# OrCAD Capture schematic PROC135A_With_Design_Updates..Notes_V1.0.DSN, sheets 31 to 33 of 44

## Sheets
31 31. SOC WKUP & GPMC: size C; title: SOC WKUP & GPMC
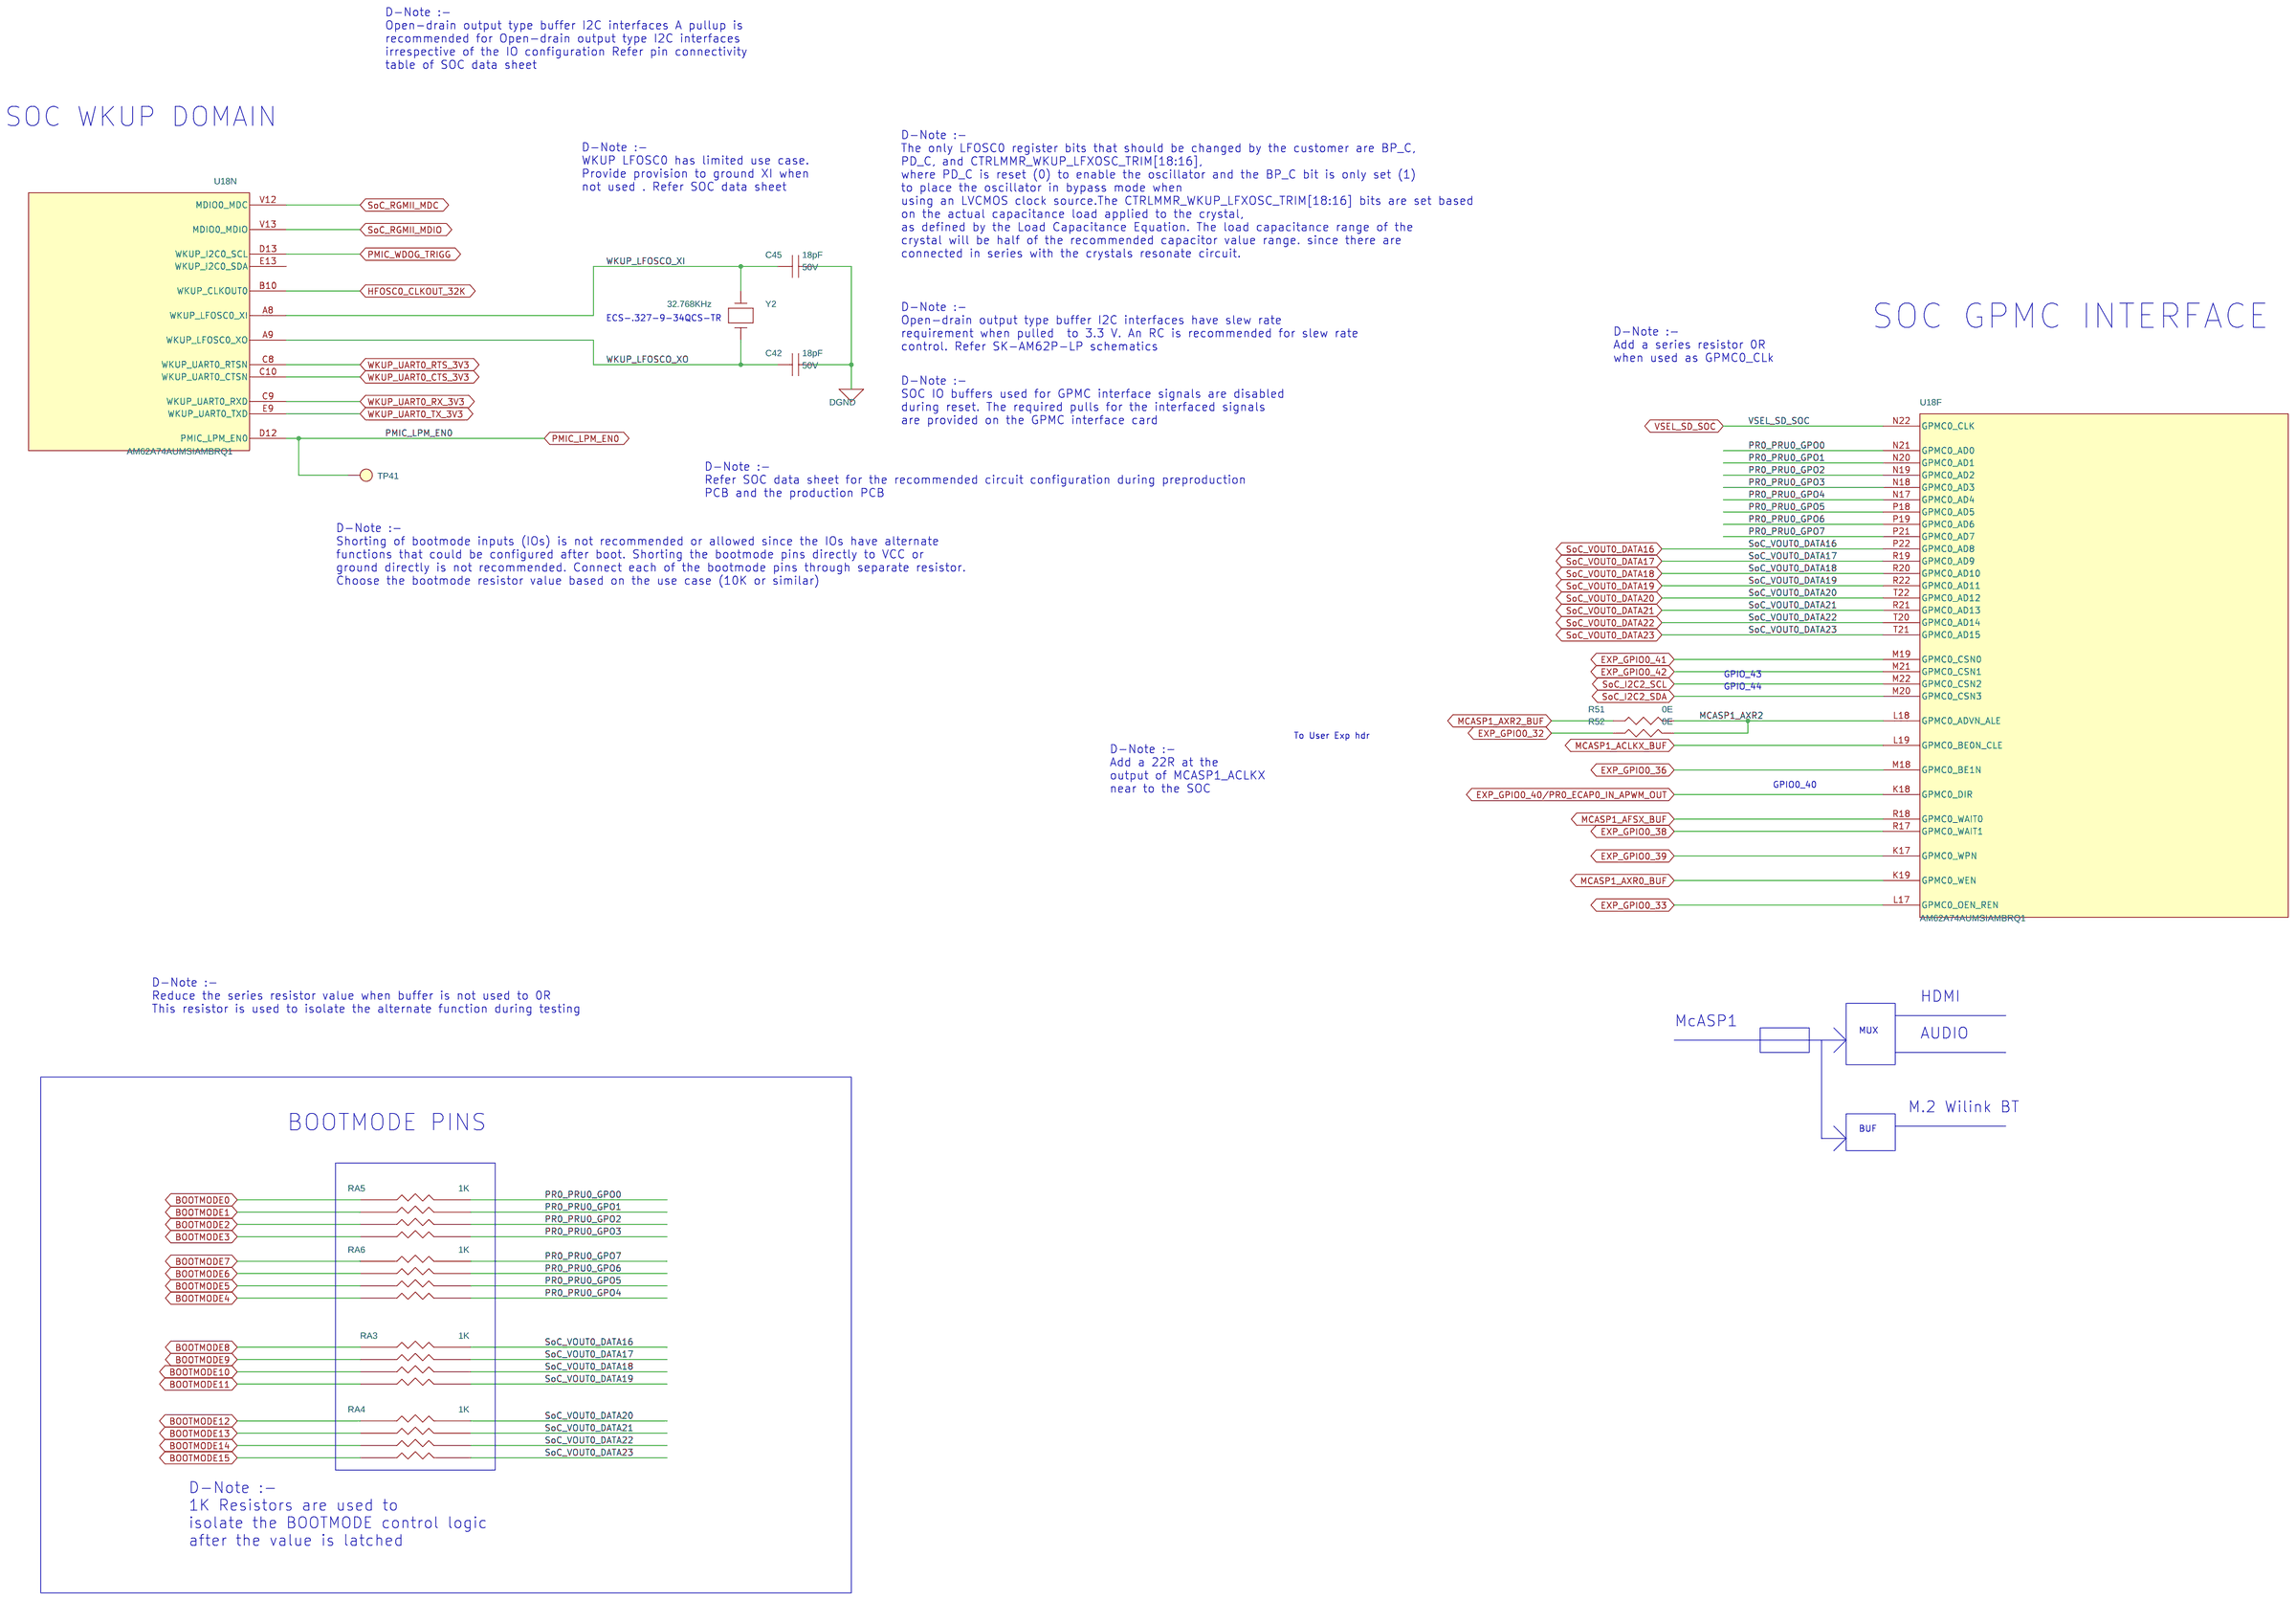
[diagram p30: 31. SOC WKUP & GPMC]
32 32. USER EXPANSION CONNECTOR: size C; title: USER EXPANSION CONNECTOR
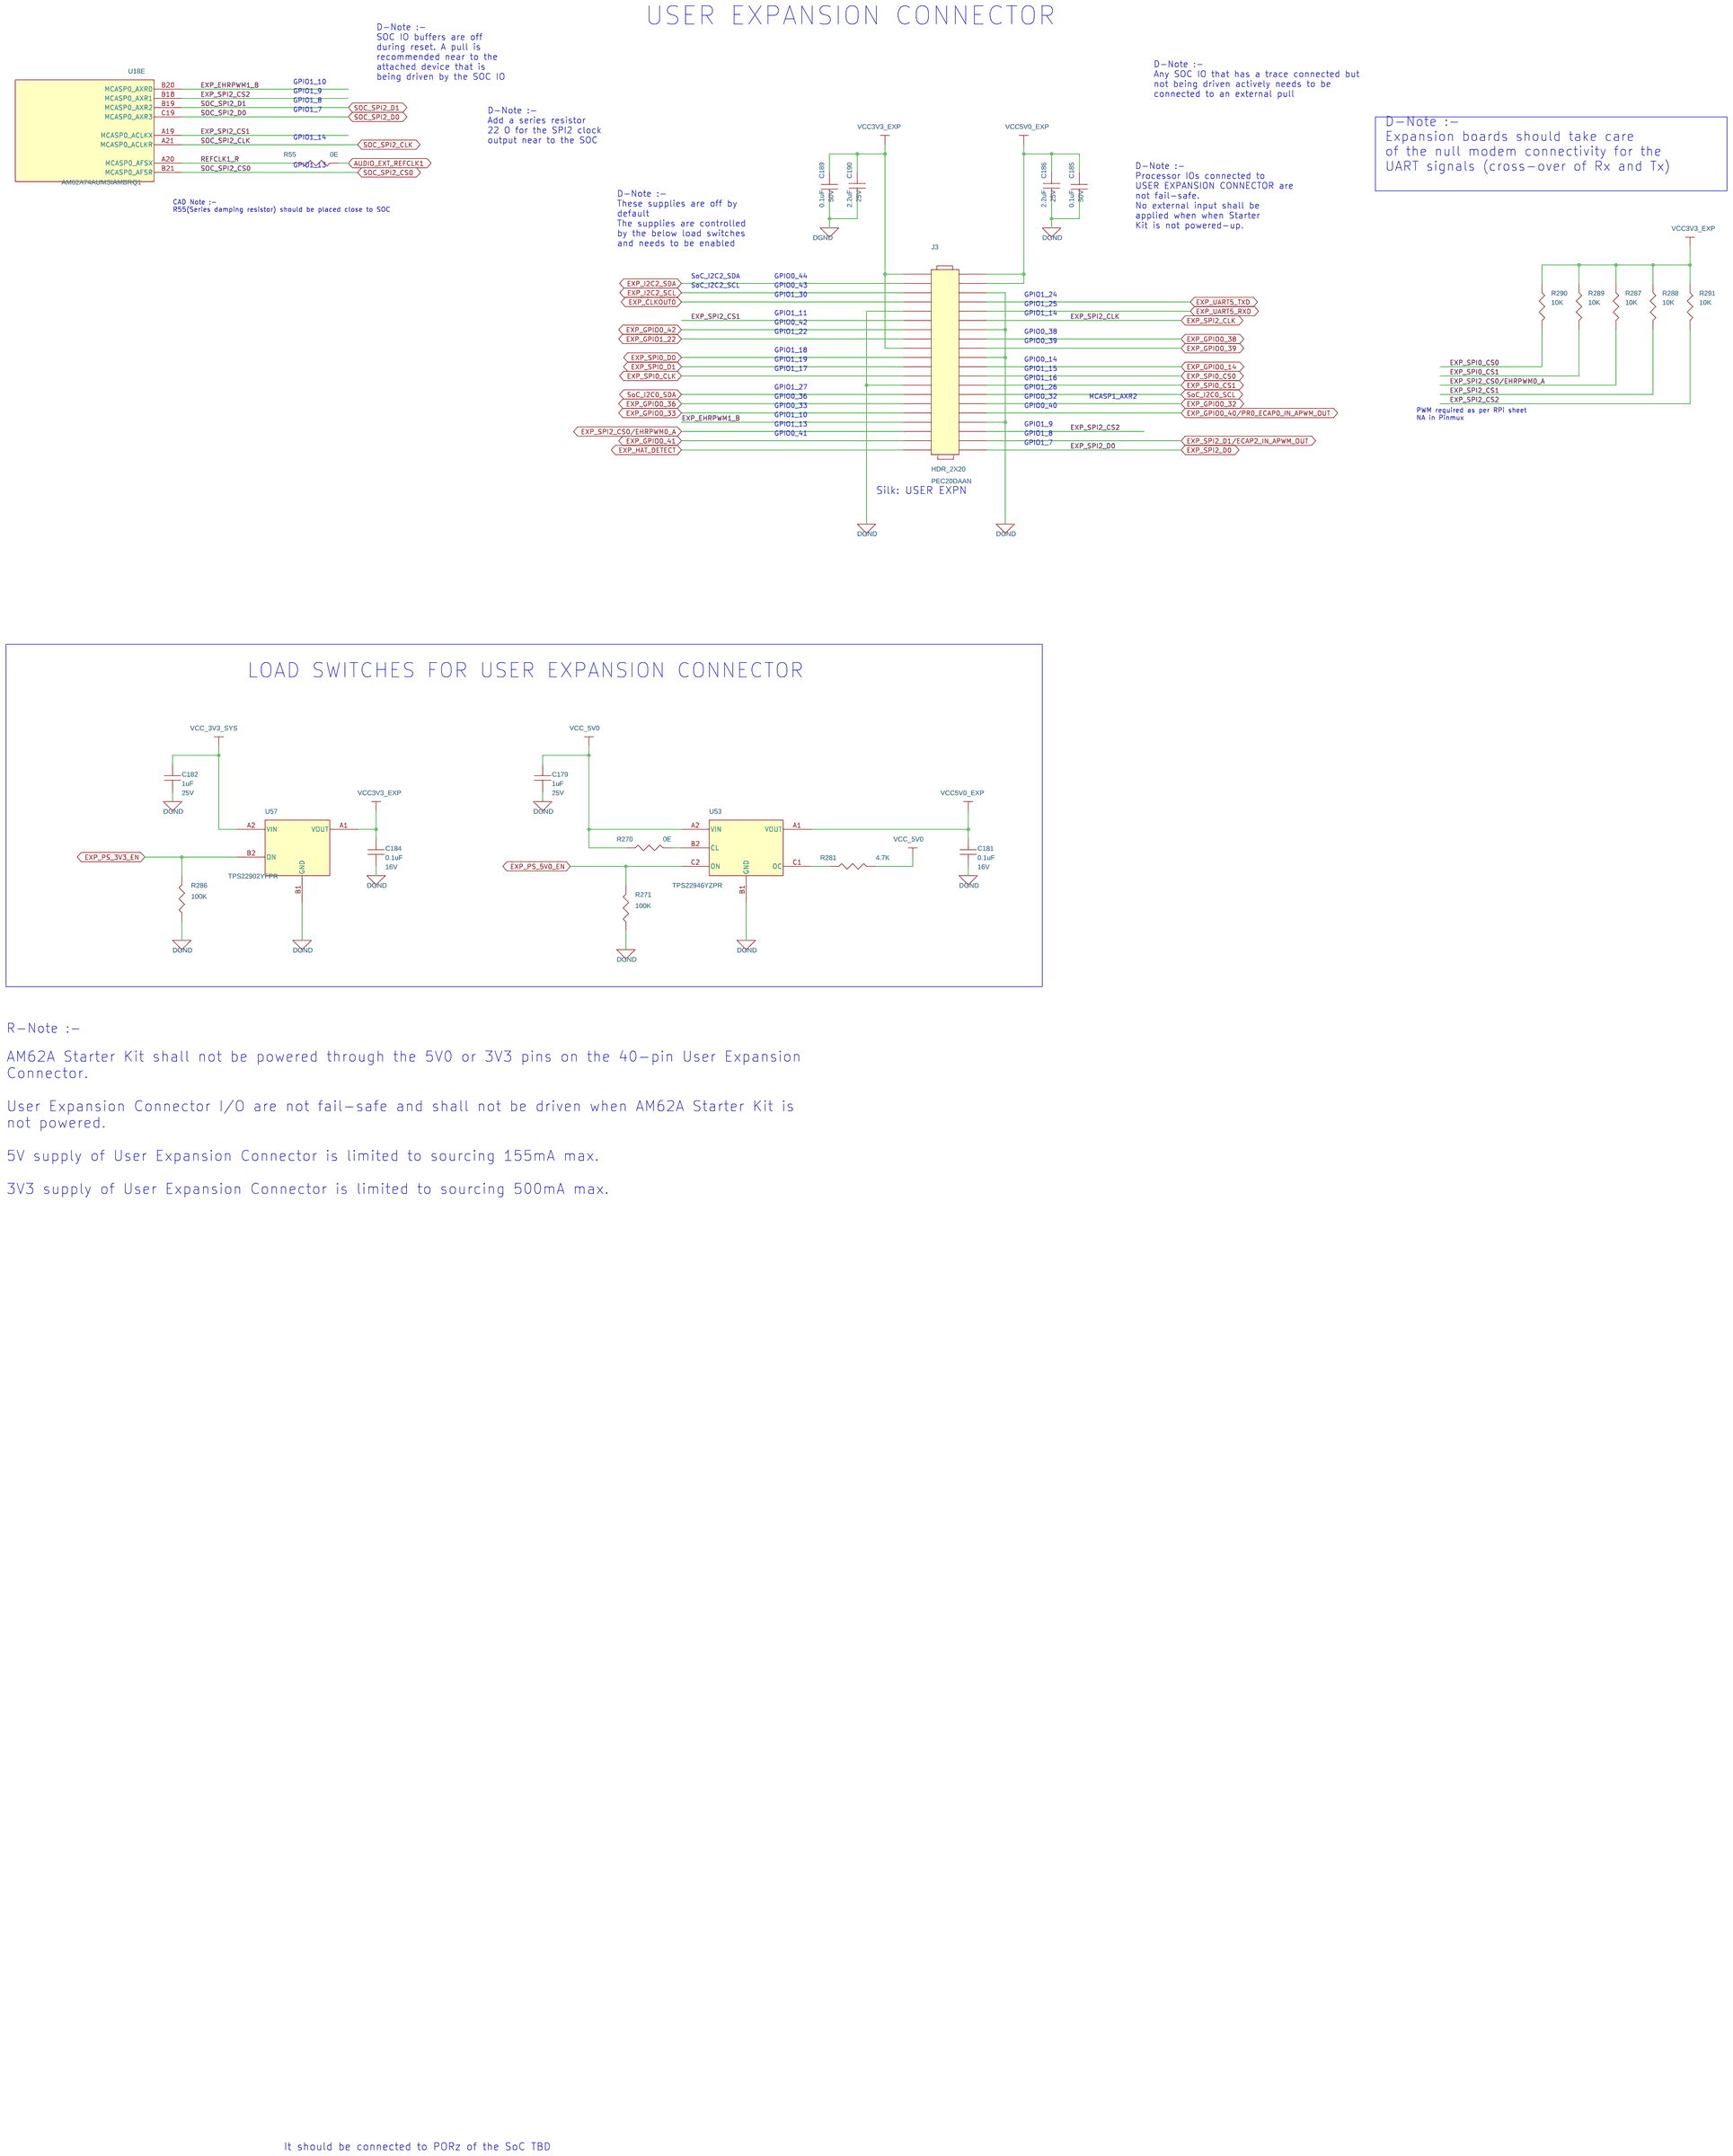
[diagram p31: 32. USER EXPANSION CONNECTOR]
33 33. MCU HEADER: size C; title: MCU HEADER
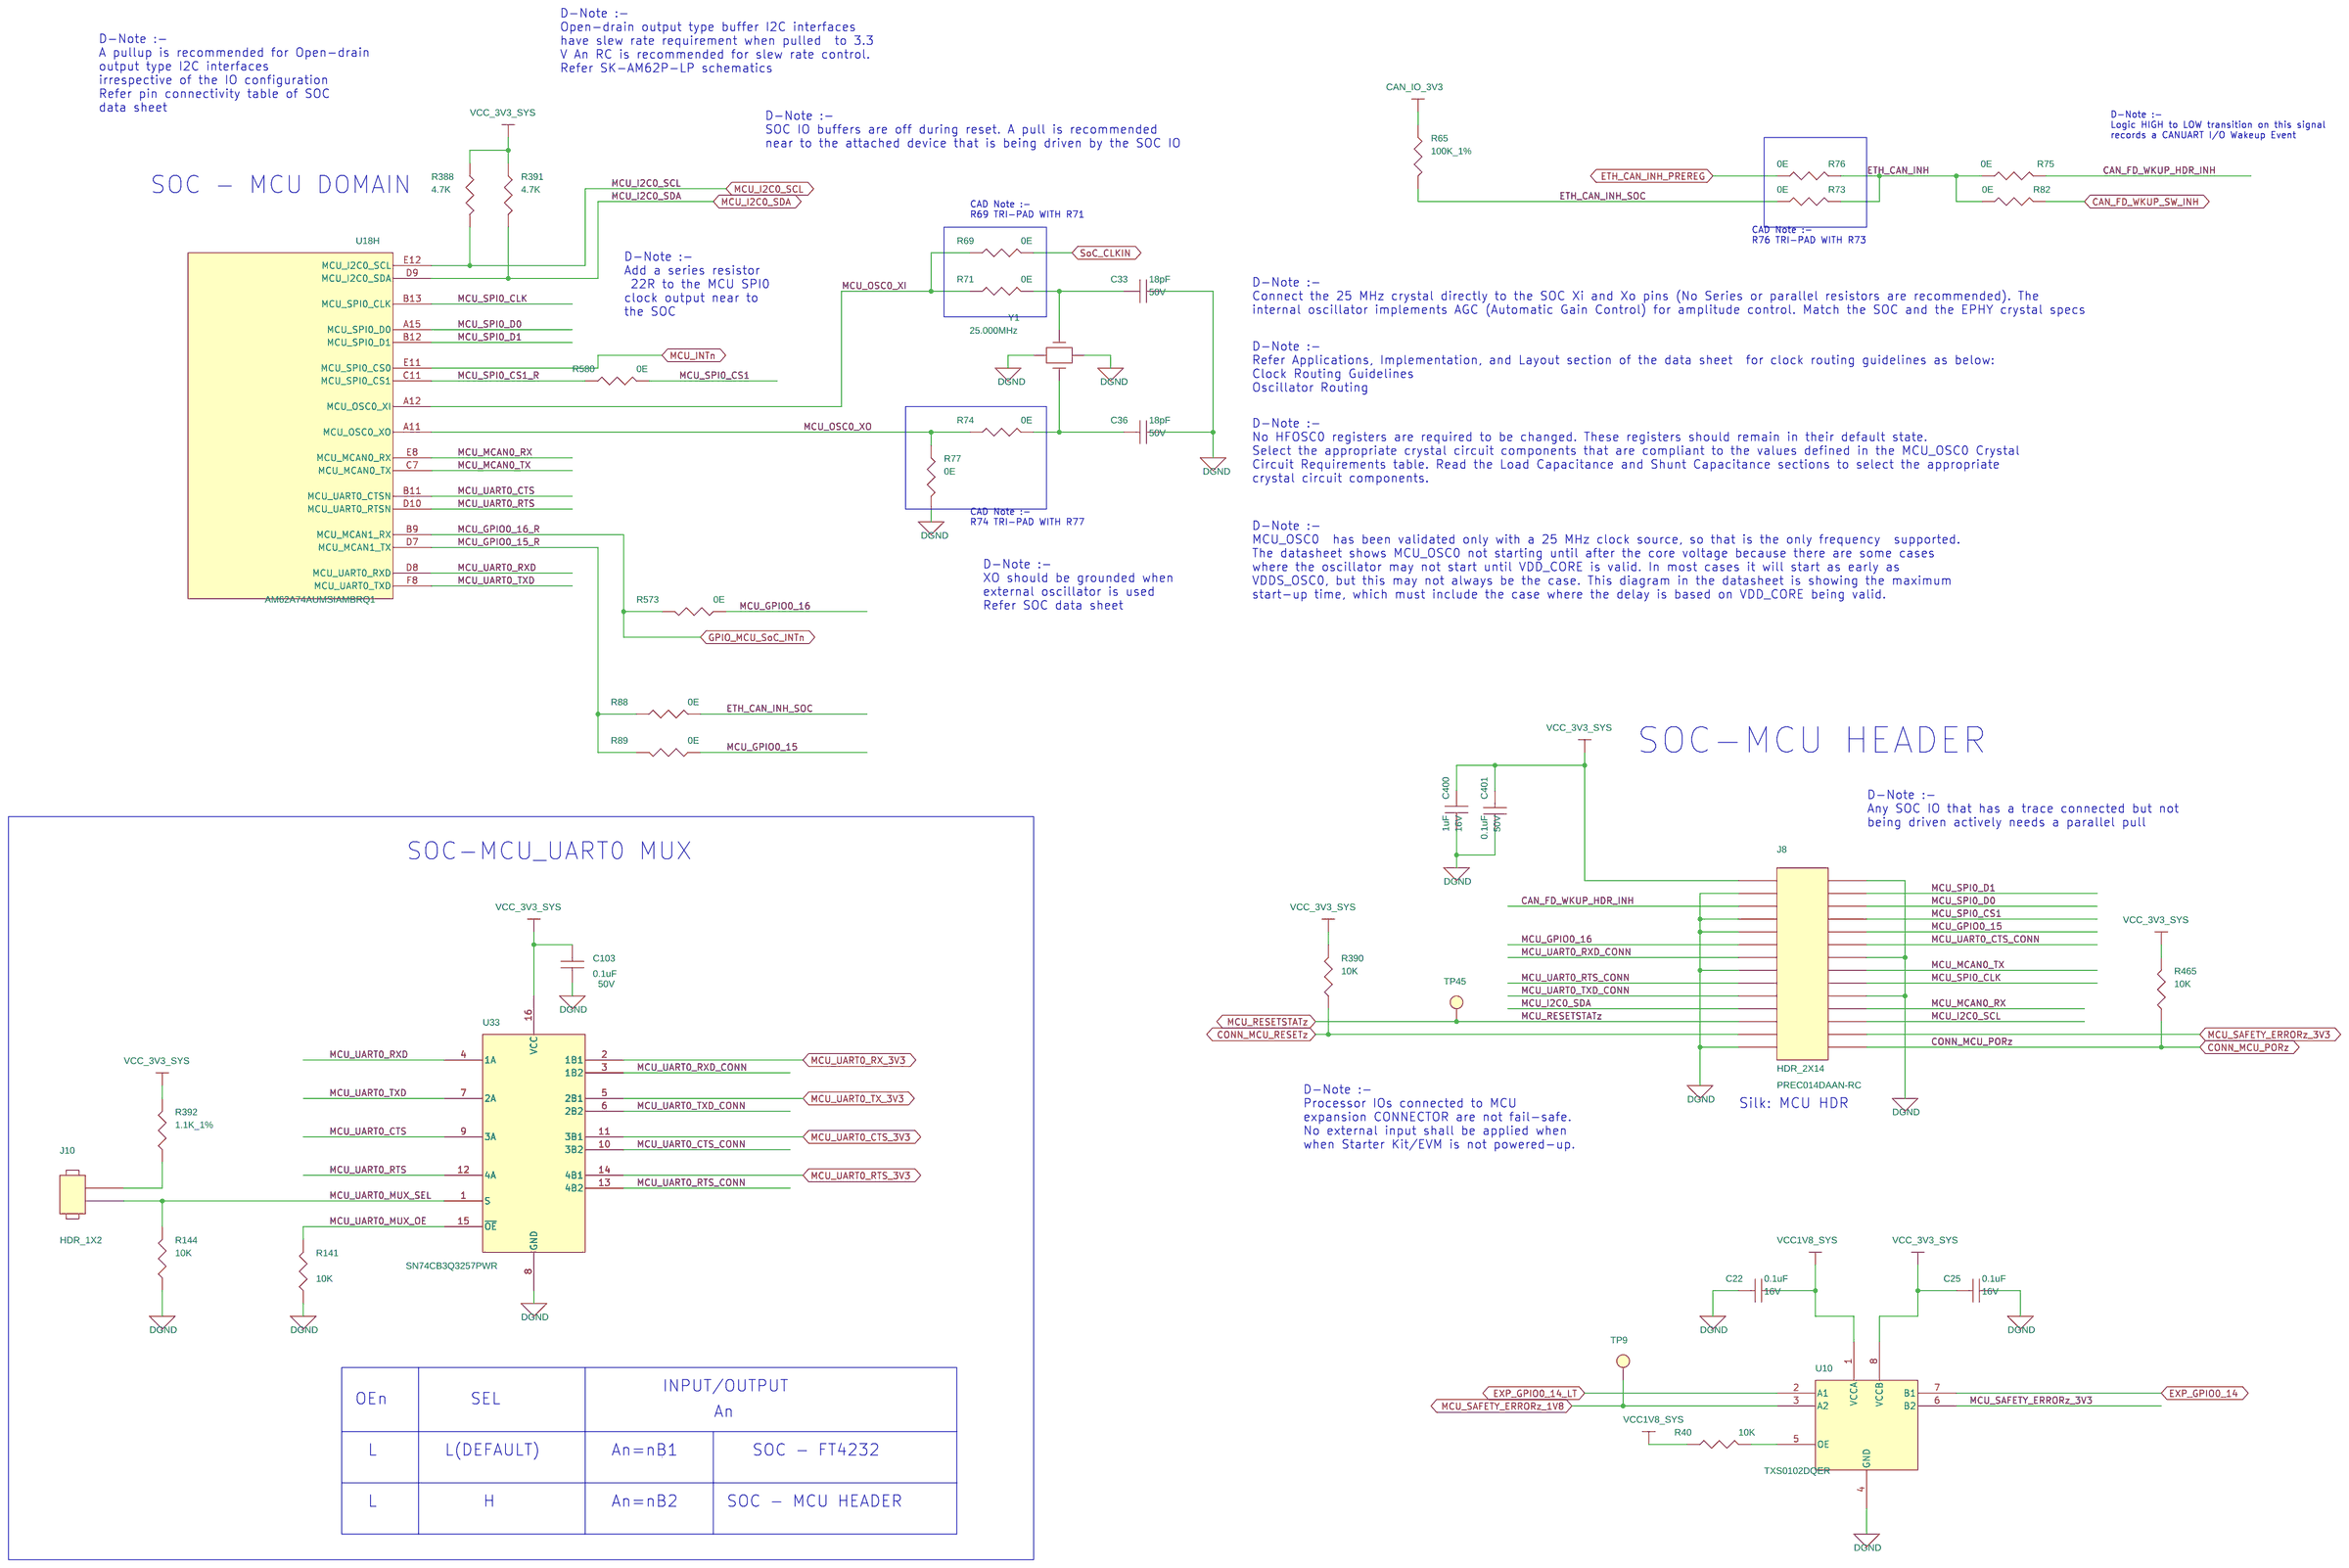
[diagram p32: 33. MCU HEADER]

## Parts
sheet 31. SOC WKUP & GPMC
C42  18pF  [CAP0402_0-75]
C45  18pF  [CAP0402_0-75]
R51  0E  [RES0201_0-5]
R52  0E  [RES0201_0-5]
RA3  1K  [RESA_EXB_0201-4_0-5]
RA4  1K  [RESA_EXB_0201-4_0-5]
RA5  1K  [RESA_EXB_0201-4_0-5]
RA6  1K  [RESA_EXB_0201-4_0-5]
TP41  TP20_SMD  [TP20_SMD]
Y2  32.768KHz  [XTAL_ECS-32_130X60_SMD_0-9]
sheet 32. USER EXPANSION CONNECTOR
C179  1uF  [CAP0402_0-75]
C181  0.1uF  [CAP0201_0-5]
C182  1uF  [CAP0402_0-75]
C184  0.1uF  [CAP0201_0-5]
C185  0.1uF  [CAP0402_0-75]
C186  2.2uF  [CAP0402_0-75]
C189  0.1uF  [CAP0402_0-75]
C190  2.2uF  [CAP0402_0-75]
J3  HDR_2X20  [HDR_2X20_PEC20DAAN_S_T_8-6]
R55  0E  [RES0201_0-5]
R270  0E  [RES0201_0-5]
R271  100K  [RES0201_0-5]
R281  4.7K  [RES0201_0-5]
R286  100K  [RES0201_0-5]
R287  10K  [RES0201_0-5]
R288  10K  [RES0201_0-5]
R289  10K  [RES0201_0-5]
R290  10K  [RES0201_0-5]
R291  10K  [RES0201_0-5]
U53  TPS22946YZPR  [DSBGA6_19-68_40X60_0-5]
U57  TPS22902YFPR  [DSBGA4_15-74_30X30_0-5]
sheet 33. MCU HEADER
C22  0.1uF  [CAP0201_0-5]
C25  0.1uF  [CAP0201_0-5]
C33  18pF  [CAP0402_0-75]
C36  18pF  [CAP0402_0-75]
C103  0.1uF  [CAP0402_0-75]
C400  1uF  [CAP0201_0-5]
C401  0.1uF  [CAP0402_0-75]
J8  HDR_2X14  [HDR_14X2_100_S_T]
J10  HDR_1X2  [HDR_1X2_90120-0122_S_T_5-6]
R40  10K  [RES0201_0-5]
R65  100K_1%  [RES0402_0-5]
R69  0E  [RES0201_0-5]
R71  0E  [RES0201_0-5]
R73  0E  [RES0201_0-5]
R74  0E  [RES0201_0-5]
R75  0E  [RES0201_0-5]
R76  0E  [RES0201_0-5]
R77  0E  [RES0201_0-5]
R82  0E  [RES0201_0-5]
R88  0E  [RES0201_0-5]
R89  0E  [RES0201_0-5]
R141  10K  [RES0201_0-5]
R144  10K  [RES0201_0-5]
R388  4.7K  [RES0201_0-5]
R390  10K  [RES0201_0-5]
R391  4.7K  [RES0201_0-5]
R392  1.1K_1%  [RES0201_0-5]
R465  10K  [RES0201_0-5]
R573  0E  [RES0201_0-5]
R580  0E  [RES0201_0-5]
TP9  TP20_SMD  [TP20_SMD]
TP45  TP20_SMD  [TP20_SMD]
U10  TXS0102DQER  [X2SON8_TXS0102_40X60_0-4]
U33  SN74CB3Q3257PWR  [TSSOP16_25-59_205X180]
Y1  25.000MHz  [XTAL4_XRCGB-FM_80X60_SMD_0-7]
sheet 41. OSCILLATOR
U18  AM62A74AUMSIAMBRQ1  [FBGA484_31-49_710X710_2-7]  (sections A,B,C,D,E,F,G,H,I,J,K,L,M,N,O,P,Q)

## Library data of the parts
C33 C36 C42 C45 = CAP: CAP CERAMIC 18pF 50V 5% HI-Q C0G(NP0) 0402; Chkd/date: VASANTHA/030315; Crtd /date: NAVEED/271014; Custom_Duty: 15%; Customs_HS_Code: 85322990; Distributor_name: DIGIKEY; Distributor_part_number: 490-3119-1-ND; Footprint Path: Y:\MIS_DATABASE\Library\ALTIUM_TOOL\PCB_FOOTPRINTS\Altium_Footprint_Lib.PcbLib; Height: 0.55MM; Library Path: Y:\MIS_DATABASE\Library\ALTIUM_TOOL\SCHEMATICS_PARTS\MS_DISCRETE_Library.schlib; Mfr_name: MURATA; Mfr_part_number: GJM1555C1H180JB01D; Mistral Part No: 120014100019-R; Package: 0402; Part_type: CAPACITORS\CERAMIC; Project: DC_MIST_RDC; RoHS: RoHS; Temperature: -55°C+125°C; Tolerance: 5%; Voltage: 50V; Wattage: NA; Weight: 6mg; Datasheet: Y:\MIS_DATABASE\DATASHEETS\CAPACITORS\MURATA-GXX-SER_NOV17.PDF
R51 R52 R55 R69 R71 R73-R75 R77 R88 R89 R270 R573 R580 = RESISTOR: RES 0E 1/20W 5% 0201; Chkd/date: NAVEED/301214; Crtd /date: MUDDU/120710; Custom_Duty: 15%; Customs_HS_Code: 85332119; Distributor_name: DIGIKEY; Distributor_part_number: 311-0.0NCT-ND; Footprint Path: Y:\MIS_DATABASE\Library\ALTIUM_TOOL\PCB_FOOTPRINTS\Altium_Footprint_Lib.PcbLib; Height: 0.26MM; Library Path: Y:\MIS_DATABASE\Library\ALTIUM_TOOL\SCHEMATICS_PARTS\MS_DISCRETE_Library.schlib; Mfr_name: YAGEO AMERICA; Mfr_part_number: RC0201JR-070RL; Mistral Part No: 110010070067-R; Package: 0201; Part_type: RESISTORS\FIXED; Project: PB_BUGBASE; RoHS: RoHS; Temperature: -55°C+125°C; Tolerance: 5%; Voltage: NA; Wattage: 1/20W; Weight: 0.17mg; Datasheet: Y:\MIS_DATABASE\DATASHEETS\RESISTORS\RCXXXXL-SER_MAR18.PDF
RA3-RA6 = RESARR_ISO4: RES ARRAY 1K 31mW 5% 0201-4; Chkd/date: NAVEED/110515; Crtd /date: VASANTHA/080515; Custom_Duty: 15%; Customs_HS_Code: 85332119; Distributor_name: DIGIKEY; Distributor_part_number: Y6102CT-ND; Footprint Path: Y:\MIS_DATABASE\Library\ALTIUM_TOOL\PCB_FOOTPRINTS\Altium_Footprint_Lib.PcbLib; Height: 0.45MM; Library Path: Y:\MIS_DATABASE\Library\ALTIUM_TOOL\SCHEMATICS_PARTS\MS_DISCRETE_Library.schlib; Mfr_name: PANASONIC-ECG; Mfr_part_number: EXB-18V102JX; Mistral Part No: 110015050003-R; Package: 0201-4; Part_type: RESISTORS\ARRAY; Project: FREE SCALE NANO; RoHS: RoHS; Temperature: -55°C+125°C; Tolerance: 5%; Voltage: NA; Wattage: 31mW; Weight: 1mg; Datasheet: Y:\MIS_DATABASE\DATASHEETS\RESISTORS\EXB-18V.PDF
TP9 TP41 TP45 = TESTPOINT: TESTPOINT CIR 20 SMD; Chkd/date: SHREESHAIL/171006; Crtd /date: MAZHAR/171006; Custom_Duty: NA; Customs_HS_Code: NA; Distributor_name: NA; Distributor_part_number: NA; Footprint Path: Y:\MIS_DATABASE\Library\ALTIUM_TOOL\PCB_FOOTPRINTS\Altium_Footprint_Lib.PcbLib; Height: NA; Library Path: Y:\MIS_DATABASE\Library\ALTIUM_TOOL\SCHEMATICS_PARTS\MS_DISCRETE_Library.schlib; MECHANICAL 3D STEP FILE: NA; Mfr_name: LOCAL; Mistral Part No: NA; Package: SMD; Project: BT MODULE_CSRBC04; RoHS: NA; Temperature: NA; Tolerance: NA; Voltage: NA; Wattage: NA; Weight: NA; Datasheet: NA
Y2 = CRY: CRY 32.768KHz 9pF SMD; Chkd/date: VASANTHA/090419; Crtd /date: ALVY/090419; Custom_Duty: 24%; Customs_HS_Code: 85439000; Distributor_name: DIGIKEY; Distributor_part_number: XC2160CT-ND; Footprint Path: Y:\MIS_DATABASE\Library\ALTIUM_TOOL\PCB_FOOTPRINTS\Altium_Footprint_Lib.PcbLib; Height: 0.90MM; Library Path: Y:\MIS_DATABASE\Library\ALTIUM_TOOL\SCHEMATICS_PARTS\MS_DISCRETE_Library.schlib; Mfr_name: ECS INC; Mfr_part_number: ECS-.327-9-34QCS-TR; Mistral Part No: 130019040003-R; Package: SMD; Part_type: CRYSTAL; Project: J7ES_SOM_DUAL-LEO_PMIC; RoHS: RoHS; Temperature: -40°C+125°C; Tolerance: NA; Voltage: NA; Wattage: NA; Weight: 16mg; Datasheet: Y:\MIS_DATABASE\DATASHEETS\MISC\CRY_OSC\ECS-34Q.PDF
C179 C182 = CAP: CAP CERAMIC 1uF 25V 10% X6S 0402; Chkd/date: MANIRAJA/140518; Crtd /date: ALVY/140518; Custom_Duty: 15%; Customs_HS_Code: 85322990; Distributor_name: DIGIKEY; Distributor_part_number: 490-10014-1-ND; Footprint Path: Y:\MIS_DATABASE\Library\ALTIUM_TOOL\PCB_FOOTPRINTS\Altium_Footprint_Lib.PcbLib; Height: 0.60MM; Library Path: Y:\MIS_DATABASE\Library\ALTIUM_TOOL\SCHEMATICS_PARTS\MS_DISCRETE_Library.schlib; Mfr_name: MURATA; Mfr_part_number: GRM155C81E105KE11D; Mistral Part No: 120018050004-R; Package: 0402; Part_type: CAPACITORS\CERAMIC; Project: TI_SVB_MAXWELL_DUT; RoHS: RoHS; Temperature: -55°C+105°C; Tolerance: 10%; Voltage: 25V; Wattage: NA; Weight: 6mg; Datasheet: Y:\MIS_DATABASE\DATASHEETS\CAPACITORS\GRM155C81E105KE11X.PDF
C181 C184 = CAP: CAP CERAMIC 0.1uF 16V 10% X5R 0201; Chkd/date: MANIRAJA/230118; Crtd /date: MANIRAJA/230118; Custom_Duty: 15%; Customs_HS_Code: 85322990; Distributor_name: DIGIKEY; Distributor_part_number: 490-14305-1-ND; Footprint Path: Y:\MIS_DATABASE\Library\ALTIUM_TOOL\PCB_FOOTPRINTS\Altium_Footprint_Lib.PcbLib; Height: 0.33MM; Library Path: Y:\MIS_DATABASE\Library\ALTIUM_TOOL\SCHEMATICS_PARTS\MS_DISCRETE_Library.schlib; Mfr_name: MURATA; Mfr_part_number: GRM033R61C104KE14D; Mistral Part No: 120009030072-R; Package: 0201; Part_type: CAPACITORS\CERAMIC; Project: TI_MAXIE_CPB; RoHS: RoHS; Temperature: -55°C+85°C; Tolerance: 10%; Voltage: 16V; Wattage: NA; Weight: 0.33mg; Datasheet: Y:\MIS_DATABASE\DATASHEETS\CAPACITORS\GRM033R61C104KE14.PDF
C103 C185 C189 C401 = CAP: CAP CERAMIC 0.1uF 50V 10% X7R 0402; Alt_Mfr_name: YAGEO AMERICA; Alt_Mfr_part_number: CC0402KRX5R8BB104; Chkd/date: MANIRAJA/261020; Crtd /date: ALVY/211020; Custom_Duty: 15%; Customs_HS_Code: 85322990; Distributor_name: DIGIKEY; Distributor_part_number: 490-10700-1-ND; Footprint Path: Y:\MIS_DATABASE\Library\ALTIUM_TOOL\PCB_FOOTPRINTS\Altium_Footprint_Lib.PcbLib; Height: 0.55MM; Library Path: Y:\MIS_DATABASE\Library\ALTIUM_TOOL\SCHEMATICS_PARTS\MS_DISCRETE_Library.schlib; Mfr_name: MURATA; Mfr_part_number: GRM155R71H104KE14D; Mistral Part No: 120011100014-R; Package: 0402; Part_type: CAPACITORS\CERAMIC; Project: J7_CP; RoHS: RoHS; Temperature: -55°C+125°C; Tolerance: 10%; Voltage: 50V; Wattage: NA; Weight: 3.1mg; Datasheet: Y:\MIS_DATABASE\DATASHEETS\CAPACITORS\GRM155R71H104KE14.PDF
C186 C190 = CAP: CAP CERAMIC 2.2uF 25V 10% X5R 0402; Chkd/date: ALVY/010721; Crtd /date: MANIRAJA/010721; Custom_Duty: 15%; Customs_HS_Code: 85322990; Distributor_name: DIGIKEY; Distributor_part_number: 490-12703-1-ND; Footprint Path: Y:\MIS_DATABASE\Library\ALTIUM_TOOL\PCB_FOOTPRINTS\Altium_Footprint_Lib.PcbLib; Height: 0.70MM; Library Path: Y:\MIS_DATABASE\Library\ALTIUM_TOOL\SCHEMATICS_PARTS\MS_DISCRETE_Library.schlib; Mfr_name: MURATA; Mfr_part_number: GRM155R61E225KE11D; Mistral Part No: 120015120001-R; Package: 0402; Part_type: CAPACITORS\CERAMIC; Project: TI_AM263X_CC; RoHS: RoHS; Temperature: -55°C+85°C; Tolerance: 10%; Voltage: 25V; Wattage: NA; Weight: 1.5mg; Datasheet: Y:\MIS_DATABASE\DATASHEETS\CAPACITORS\GRM155R61E225KE11.PDF
J3 = HEADER_20X2: CON HDR 2X20 2.54MM PITCH ST TH; Chkd/date: MANIRAJA/261020; Crtd /date: MANIRAJA/261020; Custom_Duty: 24%; Customs_HS_Code: 85369090; Distributor_name: DIGIKEY; Distributor_part_number: S2012E-20-ND; Footprint Path: Y:\MIS_DATABASE\Library\ALTIUM_TOOL\PCB_FOOTPRINTS\Altium_Footprint_Lib.PcbLib; Height: 8.58MM; Library Path: Y:\MIS_DATABASE\Library\ALTIUM_TOOL\SCHEMATICS_PARTS\MS_CONNECTOR_Library.schlib; Mfr_name: SULLINS CONNECTOR; Mfr_part_number: PEC20DAAN; Mistral Part No: 150020100013-R; Package: THRU-HOLE; Part_type: CONNECTOR\HEADERS; Project: AM64X_SKEVM; RoHS: RoHS; Temperature: -65°C+125°C; Tolerance: NA; Voltage: NA; Wattage: NA; Weight: NA; Datasheet: Y:\MIS_DATABASE\DATASHEETS\CONNECTORS\XXCXXDXXN.PDF
R271 R286 = RESISTOR: RES 100K 1/20W 5% 0201; Chkd/date: MANIRAJA/050517; Crtd /date: MANIRAJA/050517; Custom_Duty: 15%; Customs_HS_Code: 85332119; Distributor_name: DIGIKEY; Distributor_part_number: 311-100KNCT-ND; Footprint Path: Y:\MIS_DATABASE\Library\ALTIUM_TOOL\PCB_FOOTPRINTS\Altium_Footprint_Lib.PcbLib; Height: 0.26MM; Library Path: Y:\MIS_DATABASE\Library\ALTIUM_TOOL\SCHEMATICS_PARTS\MS_DISCRETE_Library.schlib; Mfr_name: YAGEO AMERICA; Mfr_part_number: RC0201JR-07100KL; Mistral Part No: 110009030176-R; Package: 0201; Part_type: RESISTORS\FIXED; Project: GOLDEN-I LITE; RoHS: RoHS; Temperature: -55°C+125°C; Tolerance: 5%; Voltage: NA; Wattage: 1/20W; Weight: 0.17mg; Datasheet: Y:\MIS_DATABASE\DATASHEETS\RESISTORS\RCXXXXL-SER_MAR18.PDF
R281 R388 R391 = RESISTOR: RES 4.7K 1/20W 5% 0201; Chkd/date: MANIRAJA/200921; Crtd /date: ALVY/200921; Custom_Duty: 15%; Customs_HS_Code: 85332119; Distributor_name: DIGIKEY; Distributor_part_number: 311-4.7KNCT-ND; Footprint Path: Y:\MIS_DATABASE\Library\ALTIUM_TOOL\PCB_FOOTPRINTS\Altium_Footprint_Lib.PcbLib; Height: 0.26MM; Library Path: Y:\MIS_DATABASE\Library\ALTIUM_TOOL\SCHEMATICS_PARTS\MS_DISCRETE_Library.schlib; Mfr_name: YAGEO AMERICA; Mfr_part_number: RC0201JR-074K7L; Mistral Part No: 110021090007-R; Package: 0201; Part_type: RESISTORS\FIXED; Project: TI_AM62x SKEVM_BRD; RoHS: RoHS; Temperature: -55°C+125°C; Tolerance: 5%; Voltage: NA; Wattage: 1/20W; Weight: 0.17mg; Datasheet: Y:\MIS_DATABASE\DATASHEETS\RESISTORS\RCXXXXL-SER_MAR18.PDF
R40 R141 R144 R287-R291 R390 R465 = RESISTOR: RES 10K 1/20W 5% 0201; Chkd/date: MANIRAJA/050517; Crtd /date: MANIRAJA/050517; Custom_Duty: 15%; Customs_HS_Code: 85332119; Distributor_name: DIGIKEY; Distributor_part_number: 311-10KNCT-ND; Footprint Path: Y:\MIS_DATABASE\Library\ALTIUM_TOOL\PCB_FOOTPRINTS\Altium_Footprint_Lib.PcbLib; Height: 0.26MM; Library Path: Y:\MIS_DATABASE\Library\ALTIUM_TOOL\SCHEMATICS_PARTS\MS_DISCRETE_Library.schlib; Mfr_name: YAGEO AMERICA; Mfr_part_number: RC0201JR-0710KL; Mistral Part No: 110010070051-R; Package: 0201; Part_type: RESISTORS\FIXED; Project: GOLDEN-I LITE; RoHS: RoHS; Temperature: -55°C+125°C; Tolerance: 5%; Voltage: NA; Wattage: 1/20W; Weight: 0.17mg; Datasheet: Y:\MIS_DATABASE\DATASHEETS\RESISTORS\RCXXXXL-SER_MAR18.PDF
U53 = TPS22946_DSBGA6: IC CURRENT-LIMITED LOAD SWITCH WITH SHUTOFF AUTO-RESTART AND OVERCURRENT CONDITION TIME-OUT DSBGA6; Chkd/date: MANIRAJA/220121; Crtd /date: ALVY/220121; Custom_Duty: 15%; Customs_HS_Code: 85423100; Distributor_name: DIGIKEY; Distributor_part_number: 296-25219-1-ND; Footprint Path: Y:\MIS_DATABASE\Library\ALTIUM_TOOL\PCB_FOOTPRINTS\Altium_Footprint_Lib.PcbLib; Height: 0.50MM; Library Path: Y:\MIS_DATABASE\Library\ALTIUM_TOOL\SCHEMATICS_PARTS\MS_MISCPOWER_Library.schlib; Mfr_name: TEXAS INSTRUMENTS; Mistral Part No: 142021010016-R; Package: DSBGA6; Part_type: ICS\POWER\MANAGEMENT; Project: AM64X_SKEVM; RoHS: RoHS; Temperature: -40°C+85°C; Tolerance: NA; Voltage: NA; Wattage: NA; Weight: 1.7mg; Datasheet: Y:\MIS_DATABASE\DATASHEETS\ICS\POWER\TPS22946.PDF
U57 = TPS22912CYZVR_DSBGA4: IC 3.6V 500mA 78mE ON-RESISTANCE LOAD SWITCH WITH CONTROLLED TURNON DSBGA4; Chkd/date: MANIRAJA/170920; Crtd /date: ALVY/160920; Custom_Duty: 15%; Customs_HS_Code: 85423100; Distributor_name: DIGIKEY; Distributor_part_number: 296-24472-1-ND; Footprint Path: Y:\MIS_DATABASE\Library\ALTIUM_TOOL\PCB_FOOTPRINTS\Altium_Footprint_Lib.PcbLib; Height: 0.50MM; Library Path: Y:\MIS_DATABASE\Library\ALTIUM_TOOL\SCHEMATICS_PARTS\MS_MISCPOWER_Library.schlib; Mfr_name: TEXAS INSTRUMENTS; Mistral Part No: 142020090007-R; Package: DSBGA4; Part_type: ICS\POWER; Project: AM64X_SKEVM; RoHS: RoHS; Temperature: -40°C+85°C; Tolerance: NA; Voltage: NA; Wattage: NA; Weight: 0.7mg; Datasheet: Y:\MIS_DATABASE\DATASHEETS\ICS\POWER\TPS22901-2-3.PDF
C22 C25 = CAP: CAP CERAMIC 0.1uF 16V 10% X5R 0201; Alt_Mfr_name: YAGEO AMERICA; Alt_Mfr_part_number: CC0402KRX5R8BB104; Chkd/date: MANIRAJA/230118; Crtd /date: MANIRAJA/230118; Custom_Duty: 15%; Customs_HS_Code: 85322990; Distributor_name: DIGIKEY; Distributor_part_number: 490-14305-1-ND; Footprint Path: Y:\MIS_DATABASE\Library\ALTIUM_TOOL\PCB_FOOTPRINTS\Altium_Footprint_Lib.PcbLib; Height: 0.33MM; Library Path: Y:\MIS_DATABASE\Library\ALTIUM_TOOL\SCHEMATICS_PARTS\MS_DISCRETE_Library.schlib; Mfr_name: MURATA; Mfr_part_number: GRM033R61C104KE14D; Mistral Part No: 120009030072-R; Package: 0201; Part_type: CAPACITORS\CERAMIC; Project: TI_MAXIE_CPB; RoHS: RoHS; Temperature: -55°C+85°C; Tolerance: 10%; Voltage: 16V; Wattage: NA; Weight: 0.33mg; Datasheet: Y:\MIS_DATABASE\DATASHEETS\CAPACITORS\GRM033R61C104KE14.PDF
C400 = CAP: CAP CERAMIC 1uF 16V 20% X5R 0201; Chkd/date: MANIRAJA/300520; Crtd /date: ALVY/260520; Custom_Duty: 15%; Customs_HS_Code: 85322990; Distributor_name: DIGIKEY; Distributor_part_number: 490-18654-1-ND; Footprint Path: Y:\MIS_DATABASE\Library\ALTIUM_TOOL\PCB_FOOTPRINTS\Altium_Footprint_Lib.PcbLib; Height: 0.39MM; Library Path: Y:\MIS_DATABASE\Library\ALTIUM_TOOL\SCHEMATICS_PARTS\MS_DISCRETE_Library.schlib; Mfr_name: MURATA; Mfr_part_number: GRM033R61C105ME15D; Mistral Part No: 120018090038-R; Package: 0201; Part_type: CAPACITORS\CERAMIC; Project: QCS610_NANOSOM; RoHS: RoHS; Temperature: -55°C+85°C; Tolerance: 20%; Voltage: 16V; Wattage: NA; Weight: 0.33mg; Datasheet: Y:\MIS_DATABASE\DATASHEETS\CAPACITORS\GRM033R61C105ME15.PDF
J8 = HEADER_14x2: CON HDR 2X14 2.54MM PITCH ST TH; Chkd/date: NAVEED/280515; Crtd /date: VASANTHA/111114; Custom_Duty: 0.24; Customs_HS_Code: 85369090; Distributor_name: DIGIKEY; Distributor_part_number: S2012EC-14-ND; Height: 8.34MM; Mfr_name: SULLINS; Mfr_part_number: PREC014DAAN-RC; Mistral Part No: 150014110005-R; Package: THRU-HOLE; Part_type: CONNECTOR\HEADERS; Project: GALILEO_EVM; RoHS: RoHS; Temperature: -40°C+105°C; Tolerance: NA; Voltage: NA; Wattage: NA; Weight: NA; Datasheet: Y:\MIS_DATABASE\DATASHEETS\CONNECTORS\PRXXXN-RC.PDF
J10 = HEADER_2X1: CON HDR 1X2 2.54MM PITCH ST TH; Chkd/date: NAVEED/210714; Crtd /date: USMAN/031012; Custom_Duty: 24%; Customs_HS_Code: 85369090; Distributor_name: DIGIKEY; Distributor_part_number: WM8072-ND; Footprint Path: Y:\MIS_DATABASE\Library\ALTIUM_TOOL\PCB_FOOTPRINTS\Altium_Footprint_Lib.PcbLib; Height: 5.60MM; Library Path: Y:\MIS_DATABASE\Library\ALTIUM_TOOL\SCHEMATICS_PARTS\MS_CONNECTOR_Library.schlib; Mfr_name: MOLEX; Mfr_part_number: 90120-0122; Mistral Part No: 150012100005-R; Package: THRU-HOLE; Part_type: CONNECTOR\HEADERS; Project: NPOL_FEP; RoHS: RoHS; Temperature: -55°C+125°C; Tolerance: NA; Voltage: NA; Wattage: NA; Weight: 122mg; Datasheet: Y:\MIS_DATABASE\DATASHEETS\CONNECTORS\90120-XX.PDF
R65 = RESISTOR: RES 100K 1/10W 1% 0402; Chkd/date: VASANTHA/201216; Crtd /date: MAZHAR/130306; Custom_Duty: 15%; Customs_HS_Code: 85332119; Distributor_name: DIGIKEY; Distributor_part_number: P100KLCT-ND; Footprint Path: Y:\MIS_DATABASE\Library\ALTIUM_TOOL\PCB_FOOTPRINTS\Altium_Footprint_Lib.PcbLib; Height: 0.40MM; Library Path: Y:\MIS_DATABASE\Library\ALTIUM_TOOL\SCHEMATICS_PARTS\MS_DISCRETE_Library.schlib; Mfr_name: PANASONIC-ECG; Mfr_part_number: ERJ-2RKF1003X; Mistral Part No: 110009030187-R; Package: 0402; Part_type: RESISTORS\FIXED; Project: J32; RoHS: RoHS; Temperature: -55°C+155°C; Tolerance: 1%; Voltage: NA; Wattage: 1/10W; Weight: 0.8mg; Datasheet: Y:\MIS_DATABASE\DATASHEETS\RESISTORS\PAN-ERJSER_NOV17.PDF
R76 R82 = RESISTOR: RES 0E 1/20W 5% 0201; Chkd/date: NAVEED/301214; Crtd /date: MUDDU/120710; Custom_Duty: 15%; Customs_HS_Code: 85332119; Distributor_name: DIGIKEY; Distributor_part_number: 311-0.0NCT-ND; Footprint Path: Y:\MIS_DATABASE\Library\ALTIUM_TOOL\PCB_FOOTPRINTS\Altium_Footprint_Lib.PcbLib; Height: 0.26MM; Library Path: Y:\MIS_DATABASE\Library\ALTIUM_TOOL\SCHEMATICS_PARTS\MS_DISCRETE_Library.schlib; Manufacturer: YAGEO AMERICA; Mfr_name: YAGEO AMERICA; Mfr_part_number: RC0201JR-070RL; Mistral Part No: 110010070067-R; Package: 0201; Part_type: RESISTORS\FIXED; Project: PB_BUGBASE; RoHS: RoHS; Temperature: -55°C+125°C; Tolerance: 5%; Voltage: NA; Wattage: 1/20W; Weight: 0.17mg; Datasheet: Y:\MIS_DATABASE\DATASHEETS\RESISTORS\RCXXXXL-SER_MAR18.PDF
R392 = RESISTOR: RES 1.1K 1/20W 1% 0201; Chkd/date: MANIRAJA/270721; Crtd /date: ALVY/260721; Custom_Duty: 15%; Customs_HS_Code: 85332119; Distributor_name: DIGIKEY; Distributor_part_number: YAG2474CT-ND; Footprint Path: Y:\MIS_DATABASE\Library\ALTIUM_TOOL\PCB_FOOTPRINTS\Altium_Footprint_Lib.PcbLib; Height: 0.26MM; Library Path: Y:\MIS_DATABASE\Library\ALTIUM_TOOL\SCHEMATICS_PARTS\MS_DISCRETE_Library.schlib; Mfr_name: YAGEO AMERICA; Mfr_part_number: RC0201FR-071K1L; Mistral Part No: 110009030097-R; Package: 0201; Part_type: RESISTORS\FIXED; Project: TI_AM335x SK_BRD; RoHS: RoHS; Temperature: -55°C+125°C; Tolerance: 1%; Voltage: NA; Wattage: 1/20W; Weight: 0.17mg; Datasheet: Y:\MIS_DATABASE\DATASHEETS\RESISTORS\RCXXXXL-SER_MAR18.PDF
U10 = TXS0102DQX_SON8: IC 2-BIT BI-DIR VOLTAGE-LEVEL TRANSLATOR FOR OPEN-DRAIN AND PUSH-PULL X2SON8; Chkd/date: MANIRAJA/010719; Crtd /date: CHAITHANYA230512; Custom_Duty: 15%; Customs_HS_Code: 85423100; Distributor_name: DIGIKEY; Distributor_part_number: 296-28368-1-ND; Footprint Path: Y:\MIS_DATABASE\Library\ALTIUM_TOOL\PCB_FOOTPRINTS\Altium_Footprint_Lib.PcbLib; Height: 0.40MM; Library Path: Y:\MIS_DATABASE\Library\ALTIUM_TOOL\SCHEMATICS_PARTS\MS_MISCINTERFACE_Library.schlib; Mfr_name: TEXAS INSTRUMENTS; Mistral Part No: 141012050010-R; Package: X2SON8; Part_type: ICS\INTERFACE\LEVEL TRANSLATOR; Project: GEN_3-8_DB; RoHS: RoHS; Temperature: -40°C+85°C; Tolerance: NA; Voltage: NA; Wattage: NA; Weight: 1.2mg; Datasheet: Y:\MIS_DATABASE\DATASHEETS\ICS\INTERFACE\TXS0102-SER.PDF
U33 = SN74CB3Q3257PWR_TSSOP16: IC 4BIT 1-OF-2 FET MULTIPLEXER/DEMULTIPLEXER TSSOP16; Chkd/date: SUHAS/251010; Crtd /date: USMAN/060109; Custom_Duty: 15%; Customs_HS_Code: 85423100; Distributor_name: DIGIKEY; Distributor_part_number: 296-19138-1-ND; Height: 1.20MM; Mfr_name: TEXAS INSTRUMENTS; Mistral Part No: 141009030117-R; Package: TSSOP16; Part_type: ICS\DIGITAL\COMBINATIONAL; Project: OMAP_EVM; RoHS: Sb/ Br FREE; Temperature: -40°C+85°C; Datasheet: Y:\MIS_DATABASE\DATASHEETS\ICS\DIGITAL\COMBINATIONAL\SN74CB3Q3257.PDF
Y1 = CRY4_13: CRY 25.000MHz 6pF SMD; Chkd/date: MANIRAJA/151020; Crtd /date: ALVY/151020; Custom_Duty: 24%; Customs_HS_Code: 85439000; Distributor_name: DIGIKEY; Distributor_part_number: 490-5578-1-ND; Footprint Path: Y:\MIS_DATABASE\Library\ALTIUM_TOOL\PCB_FOOTPRINTS\Altium_Footprint_Lib.PcbLib; Height: 0.70MM; Library Path: Y:\MIS_DATABASE\Library\ALTIUM_TOOL\SCHEMATICS_PARTS\MS_DISCRETE_Library.schlib; Mfr_name: MURATA; Mfr_part_number: XRCGB25M000F3M00R0; Mistral Part No: 130020100043-R; Package: SMD; Part_type: CRYSTAL; Project: AM64X_SKEVM; RoHS: RoHS; Temperature: -30°C+85°C; Tolerance: NA; Voltage: NA; Wattage: NA; Weight: 23mg; Datasheet: Y:\MIS_DATABASE\DATASHEETS\MISC\CRY_OSC\XRCGB.PDF
U18 = AM62A-EVM_SOC_FCBGA484: IC AM62A SK EVM SoC MICROPROCESSOR FCBGA484; Chkd/date: PRADEEP/020823; Crtd /date: PRADEEP/020823; Custom_Duty: 15%; Customs_HS_Code: 85423100; Distributor_name: NA; Distributor_part_number: NA; Footprint Path: Y:\MIS_DATABASE\Library\ALTIUM_TOOL\PCB_FOOTPRINTS\Altium_Footprint_Lib.PcbLib; Height: 2.65MM; Library Ref: AM62A-EVM_SoC_FCBGA484; Mfr_name: TEXAS INSTRUMENTS; Mistral Part No: 141230080001-R; Package: FCBGA484; Part_type: ICS\DIGITAL\MICROPROCESSOR; Project: TI_AM62A_SK_EVM; RoHS: NA; Temperature: NA; Tolerance: NA; Voltage: NA; Wattage: NA; Weight: NA; Datasheet: Y:\MIS_DATABASE\DATASHEETS\ICS\DIGITAL\MICROCONTROLLER\AM62A_SK_EVM.PDF

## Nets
DGND: C22.2 C25.1 C33.1 C36.1 C42.2 C45.2 C103.1 C179.2 C181.2 C182.2 C184.2 C185.1 C186.2 C189.1 C190.2 C400.2 C401.1 J3.6 J3.9 J3.14 J3.20 J3.25 J3.34 J8.2 J8.3 J8.7 J8.9 J8.14 J8.15 J8.20 J8.27 R77.1 R141.2 R144.1 R271.1 R286.1 U10.4(GND) U33.8(GND) U53.B1(GND) U57.B1(GND) Y1.2 Y1.4 ; also on sheet 9 10 11 12 13 14 15 16 17 18 19 20 21 22 23 24 25 26 27 28 29 30 34 35 36 37 38 39 40 41 42 43
VCC1V8_SYS: C22.1 R40.1 U10.1(VCCA) ; also on sheet 12 13 17 18 20 36 38 39 41
VCC3V3_EXP: C184.1 C189.2 C190.1 J3.1 J3.17 R287.1 R288.1 R289.1 R290.1 R291.1 U57.A1(VOUT) ; also on sheet 37
VCC5V0_EXP: C181.1 C185.2 C186.1 J3.2 J3.4 U53.A1(VOUT)
VCC_3V3_SYS: C25.2 C103.2 C182.1 C400.1 C401.2 J8.1 R388.1 R390.2 R391.1 R392.2 R465.2 U10.8(VCCB) U33.16(VCC) U57.A2(VIN) ; also on sheet 9 10 12 13 17 18 19 21 22 23 25 26 28 29 30 34 35 36 37 38 39 40 41 42
VCC_5V0: C179.1 R270.1 R281.2 U53.A2(VIN) ; also on sheet 9 10 34 37 40
AUDIO_EXT_REFCLK1: R55.1 ; also on sheet 40
BOOTMODE0: RA5.1 ; also on sheet 26
BOOTMODE1: RA5.2 ; also on sheet 26
BOOTMODE2: RA5.3 ; also on sheet 26
BOOTMODE3: RA5.4 ; also on sheet 26
BOOTMODE4: RA6.4 ; also on sheet 26
BOOTMODE5: RA6.3 ; also on sheet 26
BOOTMODE6: RA6.2 ; also on sheet 26
BOOTMODE7: RA6.1 ; also on sheet 26
BOOTMODE8: RA3.1 ; also on sheet 26
BOOTMODE9: RA3.2 ; also on sheet 26
BOOTMODE10: RA3.3 ; also on sheet 26
BOOTMODE11: RA3.4 ; also on sheet 26
BOOTMODE12: RA4.1 ; also on sheet 26
BOOTMODE13: RA4.2 ; also on sheet 26
BOOTMODE14: RA4.3 ; also on sheet 26
BOOTMODE15: RA4.4 ; also on sheet 26
CAN_FD_WKUP_HDR_INH: J8.5 R75.1
CAN_FD_WKUP_SW_INH: R82.2 ; also on sheet 43
CAN_IO_3V3: R65.1 ; also on sheet 12 14 30 43
CONN_MCU_PORz: J8.28 R465.1 ; also on sheet 41
CONN_MCU_RESETz: J8.25 R390.1 ; also on sheet 42
ETH_CAN_INH: R73.2 R75.2 R76.2 R82.1
ETH_CAN_INH_PREREG: R76.1 ; also on sheet 11
ETH_CAN_INH_SOC: R65.2 R73.1 R88.1
EXP_CLKOUT0: J3.7 ; also on sheet 41
EXP_EHRPWM1_B: J3.33 U18.B20(MCASP0_AXR0)
EXP_GPIO0_14: J3.22 U10.7(B1)
EXP_GPIO0_14_LT: U10.2(A1) ; also on sheet 20
EXP_GPIO0_32: J3.30 R52.1
EXP_GPIO0_33: J3.31 U18.L17(GPMC0_OEN_REN)
EXP_GPIO0_36: J3.29 U18.M18(GPMC0_BE1N)
EXP_GPIO0_38: J3.16 U18.R17(GPMC0_WAIT1)
EXP_GPIO0_39: J3.18 U18.K17(GPMC0_WPN)
EXP_GPIO0_40/PR0_ECAP0_IN_APWM_OUT: J3.32 U18.K18(GPMC0_DIR)
EXP_GPIO0_41: J3.37 U18.M19(GPMC0_CSN0)
EXP_GPIO0_42: J3.13 U18.M21(GPMC0_CSN1)
EXP_GPIO1_22: J3.15 ; also on sheet 41
EXP_HAT_DETECT: J3.39 ; also on sheet 39
EXP_I2C2_SCL: J3.5 ; also on sheet 37
EXP_I2C2_SDA: J3.3 ; also on sheet 37
EXP_PS_3V3_EN: R286.2 U57.B2(ON) ; also on sheet 39
EXP_PS_5V0_EN: R271.2 U53.C2(ON) ; also on sheet 39
EXP_SPI0_CLK: J3.23 ; also on sheet 41
EXP_SPI0_CS0: J3.24 R290.2 ; also on sheet 41
EXP_SPI0_CS1: J3.26 R289.2 ; also on sheet 41
EXP_SPI0_D0: J3.19 ; also on sheet 41
EXP_SPI0_D1: J3.21 ; also on sheet 41
EXP_SPI2_CLK: J3.12 ; also on sheet 36
EXP_SPI2_CS0/EHRPWM0_A: J3.35 R287.2 ; also on sheet 36
EXP_SPI2_CS1: J3.11 R288.2 U18.A19(MCASP0_ACLKX)
EXP_SPI2_CS2: J3.36 R291.2 U18.B18(MCASP0_AXR1)
EXP_SPI2_D0: J3.40 ; also on sheet 36
EXP_SPI2_D1/ECAP2_IN_APWM_OUT: J3.38 ; also on sheet 36
EXP_UART5_RXD: J3.10 ; also on sheet 41
EXP_UART5_TXD: J3.8 ; also on sheet 41
GPIO_MCU_SoC_INTn: R573.1 U18.B9(MCU_MCAN1_RX) ; also on sheet 42
HFOSC0_CLKOUT_32K: U18.B10(WKUP_CLKOUT0) ; also on sheet 17
MCASP1_ACLKX_BUF: U18.L19(GPMC0_BE0N_CLE) ; also on sheet 39
MCASP1_AFSX_BUF: U18.R18(GPMC0_WAIT0) ; also on sheet 39
MCASP1_AXR0_BUF: U18.K19(GPMC0_WEN) ; also on sheet 39
MCASP1_AXR2: R51.2 R52.2 U18.L18(GPMC0_ADVN_ALE)
MCASP1_AXR2_BUF: R51.1 ; also on sheet 39
MCU_GPIO0_15: J8.10 R89.2
MCU_GPIO0_15_R: R88.2 R89.1 U18.D7(MCU_MCAN1_TX)
MCU_GPIO0_16: J8.11 R573.2
MCU_I2C0_SCL: J8.24 R388.2 U18.E12(MCU_I2C0_SCL) ; also on sheet 12
MCU_I2C0_SDA: J8.21 R391.2 U18.D9(MCU_I2C0_SDA) ; also on sheet 12
MCU_INTn: U18.E11(MCU_SPI0_CS0) ; also on sheet 12
MCU_MCAN0_RX: J8.22 U18.E8(MCU_MCAN0_RX)
MCU_MCAN0_TX: J8.16 U18.C7(MCU_MCAN0_TX)
MCU_OSC0_XI: R69.2 R71.2 U18.A12(MCU_OSC0_XI)
MCU_OSC0_XO: R74.2 R77.2 U18.A11(MCU_OSC0_XO)
MCU_RESETSTATz: J8.23 TP45.1(TP) ; also on sheet 41
MCU_SAFETY_ERRORz_1V8: TP9.1(TP) U10.3(A2) ; also on sheet 41
MCU_SAFETY_ERRORz_3V3: J8.26 U10.6(B2) ; also on sheet 12
MCU_SPI0_CLK: J8.18 U18.B13(MCU_SPI0_CLK)
MCU_SPI0_CS1: J8.8 R580.1
MCU_SPI0_CS1_R: R580.2 U18.C11(MCU_SPI0_CS1)
MCU_SPI0_D0: J8.6 U18.A15(MCU_SPI0_D0)
MCU_SPI0_D1: J8.4 U18.B12(MCU_SPI0_D1)
MCU_UART0_CTS: U18.B11(MCU_UART0_CTSN) U33.9(3A)
MCU_UART0_CTS_3V3: U33.11(3B1) ; also on sheet 30
MCU_UART0_CTS_CONN: J8.12 U33.10(3B2)
MCU_UART0_MUX_OE: R141.1 U33.15(~{OE})
MCU_UART0_MUX_SEL: J10.2 R144.2 U33.1(S)
MCU_UART0_RTS: U18.D10(MCU_UART0_RTSN) U33.12(4A)
MCU_UART0_RTS_3V3: U33.14(4B1) ; also on sheet 30
MCU_UART0_RTS_CONN: J8.17 U33.13(4B2)
MCU_UART0_RX_3V3: U33.2(1B1) ; also on sheet 30
MCU_UART0_RXD: U18.D8(MCU_UART0_RXD) U33.4(1A)
MCU_UART0_RXD_CONN: J8.13 U33.3(1B2)
MCU_UART0_TX_3V3: U33.5(2B1) ; also on sheet 30
MCU_UART0_TXD: U18.F8(MCU_UART0_TXD) U33.7(2A)
MCU_UART0_TXD_CONN: J8.19 U33.6(2B2)
PMIC_LPM_EN0: TP41.1(TP) U18.D12(PMIC_LPM_EN0) ; also on sheet 12
PMIC_WDOG_TRIGG: U18.D13(WKUP_I2C0_SCL) ; also on sheet 12
PR0_PRU0_GPO0: RA5.8 U18.N21(GPMC0_AD0)
PR0_PRU0_GPO1: RA5.7 U18.N20(GPMC0_AD1)
PR0_PRU0_GPO2: RA5.6 U18.N19(GPMC0_AD2)
PR0_PRU0_GPO3: RA5.5 U18.N18(GPMC0_AD3)
PR0_PRU0_GPO4: RA6.5 U18.N17(GPMC0_AD4)
PR0_PRU0_GPO5: RA6.6 U18.P18(GPMC0_AD5)
PR0_PRU0_GPO6: RA6.7 U18.P19(GPMC0_AD6)
PR0_PRU0_GPO7: RA6.8 U18.P21(GPMC0_AD7)
REFCLK1_R: R55.2 U18.A20(MCASP0_AFSX)
SoC_CLKIN: R69.1 ; also on sheet 24
SoC_I2C0_SCL: J3.28 ; also on sheet 9 12 21 41
SoC_I2C0_SDA: J3.27 ; also on sheet 9 12 21 41
SoC_I2C2_SCL: U18.M22(GPMC0_CSN2) ; also on sheet 37
SoC_I2C2_SDA: U18.M20(GPMC0_CSN3) ; also on sheet 37
SoC_RGMII_MDC: U18.V12(MDIO0_MDC) ; also on sheet 22 23
SoC_RGMII_MDIO: U18.V13(MDIO0_MDIO) ; also on sheet 22 23
SOC_SPI2_CLK: U18.A21(MCASP0_ACLKR) ; also on sheet 36
SOC_SPI2_CS0: U18.B21(MCASP0_AFSR) ; also on sheet 36
SOC_SPI2_D0: U18.C19(MCASP0_AXR3) ; also on sheet 36
SOC_SPI2_D1: U18.B19(MCASP0_AXR2) ; also on sheet 36
SoC_VOUT0_DATA16: RA3.8 U18.P22(GPMC0_AD8) ; also on sheet 40
SoC_VOUT0_DATA17: RA3.7 U18.R19(GPMC0_AD9) ; also on sheet 40
SoC_VOUT0_DATA18: RA3.6 U18.R20(GPMC0_AD10) ; also on sheet 40
SoC_VOUT0_DATA19: RA3.5 U18.R22(GPMC0_AD11) ; also on sheet 40
SoC_VOUT0_DATA20: RA4.8 U18.T22(GPMC0_AD12) ; also on sheet 40
SoC_VOUT0_DATA21: RA4.7 U18.R21(GPMC0_AD13) ; also on sheet 40
SoC_VOUT0_DATA22: RA4.6 U18.T20(GPMC0_AD14) ; also on sheet 40
SoC_VOUT0_DATA23: RA4.5 U18.T21(GPMC0_AD15) ; also on sheet 40
VSEL_SD_SOC: U18.N22(GPMC0_CLK) ; also on sheet 12
WKUP_LFOSCO_XI: C45.1 U18.A8(WKUP_LFOSC0_XI) Y2.1
WKUP_LFOSCO_XO: C42.1 U18.A9(WKUP_LFOSC0_XO) Y2.2
WKUP_UART0_CTS_3V3: U18.C10(WKUP_UART0_CTSN) ; also on sheet 30
WKUP_UART0_RTS_3V3: U18.C8(WKUP_UART0_RTSN) ; also on sheet 30
WKUP_UART0_RX_3V3: U18.C9(WKUP_UART0_RXD) ; also on sheet 30
WKUP_UART0_TX_3V3: U18.E9(WKUP_UART0_TXD) ; also on sheet 30
N16906426: C33.2 R71.1 Y1.1
N16906432: C36.2 R74.1 Y1.3
N16931396: R270.2 U53.B2(CL)
N16931420: R281.1 U53.C1(OC)
N17492093: R40.2 U10.5(OE)
N17492111: J10.1 R392.1

Not connected (* = marked no-connect by the designer): U18 E13(WKUP_I2C0_SDA)

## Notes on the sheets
sheet 31
- D-Note :-
  Open-drain output type buffer I2C interfaces A pullup is
  recommended for Open-drain output type I2C interfaces
  irrespective of the IO configuration Refer pin connectivity
  table of SOC data sheet
- SOC WKUP DOMAIN
- D-Note :-
  The only LFOSC0 register bits that should be changed by the customer are BP_C,
  PD_C, and CTRLMMR_WKUP_LFXOSC_TRIM[18:16],
  where PD_C is reset (0) to enable the oscillator and the BP_C bit is only set (1)
  to place the oscillator in bypass mode when
  using an LVCMOS clock source.The CTRLMMR_WKUP_LFXOSC_TRIM[18:16] bits are set based
  on the actual capacitance load applied to the crystal,
  as defined by the Load Capacitance Equation. The load capacitance range of the
  crystal will be half of the recommended capacitor value range. since there are
  connected in series with the crystals resonate circuit.
- D-Note :-
  WKUP LFOSC0 has limited use case.
  Provide provision to ground XI when
  not used . Refer SOC data sheet
- D-Note :-
  Open-drain output type buffer I2C interfaces have slew rate
  requirement when pulled  to 3.3 V. An RC is recommended for slew rate
  control. Refer SK-AM62P-LP schematics
- SOC GPMC INTERFACE
- ECS-.327-9-34QCS-TR
- D-Note :-
  Add a series resistor 0R
  when used as GPMC0_CLk
- D-Note :-
  SOC IO buffers used for GPMC interface signals are disabled
  during reset. The required pulls for the interfaced signals
  are provided on the GPMC interface card
- D-Note :-
  Refer SOC data sheet for the recommended circuit configuration during preproduction
  PCB and the production PCB
- D-Note :-
  Shorting of bootmode inputs (IOs) is not recommended or allowed since the IOs have alternate
  functions that could be configured after boot. Shorting the bootmode pins directly to VCC or
  ground directly is not recommended. Connect each of the bootmode pins through separate resistor.
  Choose the bootmode resistor value based on the use case (10K or similar)
- GPIO_43
- GPIO_44
- To User Exp hdr
- D-Note :-
  Add a 22R at the
  output of MCASP1_ACLKX
  near to the SOC
- GPIO0_40
- D-Note :-
  Reduce the series resistor value when buffer is not used to 0R
  This resistor is used to isolate the alternate function during testing
- HDMI
- McASP1
- MUX
- AUDIO
- M.2 Wilink BT
- BOOTMODE PINS
- BUF
- D-Note :-
  1K Resistors are used to
  isolate the BOOTMODE control logic
  after the value is latched
sheet 32
- USER EXPANSION CONNECTOR
- D-Note :-
  SOC IO buffers are off
  during reset. A pull is
  recommended near to the
  attached device that is
  being driven by the SOC IO
- D-Note :-
  Any SOC IO that has a trace connected but
  not being driven actively needs to be
  connected to an external pull
- GPIO1_10
- GPIO1_9
- GPIO1_7
- GPIO1_8
- D-Note :-
  Add a series resistor
  22 O for the SPI2 clock
  output near to the SOC
- D-Note :-
  Expansion boards should take care
  of the null modem connectivity for the
  UART signals (cross-over of Rx and Tx)
- GPIO1_14
- GPIO1_13
- D-Note :-
  Processor IOs connected to
  USER EXPANSION CONNECTOR are
  not fail-safe.
  No external input shall be
  applied when when Starter
  Kit is not powered-up.
- D-Note :-
  These supplies are off by
  default
  The supplies are controlled
  by the below load switches
  and needs to be enabled
- CAD Note :-
  R55(Series damping resistor) should be placed close to SOC
- SoC_I2C2_SCL
- SoC_I2C2_SDA
- GPIO0_43
- GPIO0_44
- GPIO1_30
- GPIO1_24
- GPIO1_25
- GPIO1_11
- GPIO1_14
- GPIO0_42
- GPIO1_22
- GPIO0_38
- GPIO1_18
- GPIO0_39
- GPIO1_19
- GPIO0_14
- GPIO1_17
- GPIO1_15
- GPIO1_16
- GPIO1_27
- GPIO1_26
- GPIO0_33
- GPIO0_36
- GPIO0_32
- GPIO0_40
- MCASP1_AXR2
- GPIO1_10
- PWM required as per RPi sheet
  NA in Pinmux
- GPIO1_13
- GPIO1_9
- GPIO0_41
- GPIO1_8
- GPIO1_7
- Silk: USER EXPN
- LOAD SWITCHES FOR USER EXPANSION CONNECTOR
- R-Note :-
- AM62A Starter Kit shall not be powered through the 5V0 or 3V3 pins on the 40-pin User Expansion
  Connector.
  User Expansion Connector I/O are not fail-safe and shall not be driven when AM62A Starter Kit is
  not powered.
  5V supply of User Expansion Connector is limited to sourcing 155mA max.
  3V3 supply of User Expansion Connector is limited to sourcing 500mA max.
- It should be connected to PORz of the SoC TBD
sheet 33
- D-Note :-
  Open-drain output type buffer I2C interfaces
  have slew rate requirement when pulled  to 3.3
  V An RC is recommended for slew rate control.
  Refer SK-AM62P-LP schematics
- D-Note :-
  A pullup is recommended for Open-drain
  output type I2C interfaces
  irrespective of the IO configuration
  Refer pin connectivity table of SOC
  data sheet
- D-Note :-
  SOC IO buffers are off during reset. A pull is recommended
  near to the attached device that is being driven by the SOC IO
- D-Note :-
  Logic HIGH to LOW transition on this signal
  records a CANUART I/O Wakeup Event
- SOC - MCU DOMAIN
- CAD Note :-
  R69 TRI-PAD WITH R71
- CAD Note :-
  R76 TRI-PAD WITH R73
- D-Note :-
  Add a series resistor
   22R to the MCU SPI0
  clock output near to
  the SOC
- D-Note :-
  Connect the 25 MHz crystal directly to the SOC Xi and Xo pins (No Series or parallel resistors are recommended). The
  internal oscillator implements AGC (Automatic Gain Control) for amplitude control. Match the SOC and the EPHY crystal specs
- D-Note :-
  Refer Applications, Implementation, and Layout section of the data sheet  for clock routing guidelines as below:
  Clock Routing Guidelines
  Oscillator Routing
- D-Note :-
  No HFOSC0 registers are required to be changed. These registers should remain in their default state.
  Select the appropriate crystal circuit components that are compliant to the values defined in the MCU_OSC0 Crystal
  Circuit Requirements table. Read the Load Capacitance and Shunt Capacitance sections to select the appropriate
  crystal circuit components.
- CAD Note :-
  R74 TRI-PAD WITH R77
- D-Note :-
  MCU_OSC0  has been validated only with a 25 MHz clock source, so that is the only frequency  supported.
  The datasheet shows MCU_OSC0 not starting until after the core voltage because there are some cases
  where the oscillator may not start until VDD_CORE is valid. In most cases it will start as early as
  VDDS_OSC0, but this may not always be the case. This diagram in the datasheet is showing the maximum
  start-up time, which must include the case where the delay is based on VDD_CORE being valid.
- D-Note :-
  XO should be grounded when
  external oscillator is used
  Refer SOC data sheet
- SOC-MCU HEADER
- D-Note :-
  Any SOC IO that has a trace connected but not
  being driven actively needs a parallel pull
- SOC-MCU_UART0 MUX
- D-Note :-
  Processor IOs connected to MCU
  expansion CONNECTOR are not fail-safe.
  No external input shall be applied when
  when Starter Kit/EVM is not powered-up.
- Silk: MCU HDR
- INPUT/OUTPUT
- OEn
- SEL
- An
- L
- L(DEFAULT)
- An=nB1
- SOC - FT4232
- L
- H
- An=nB2
- SOC - MCU HEADER
